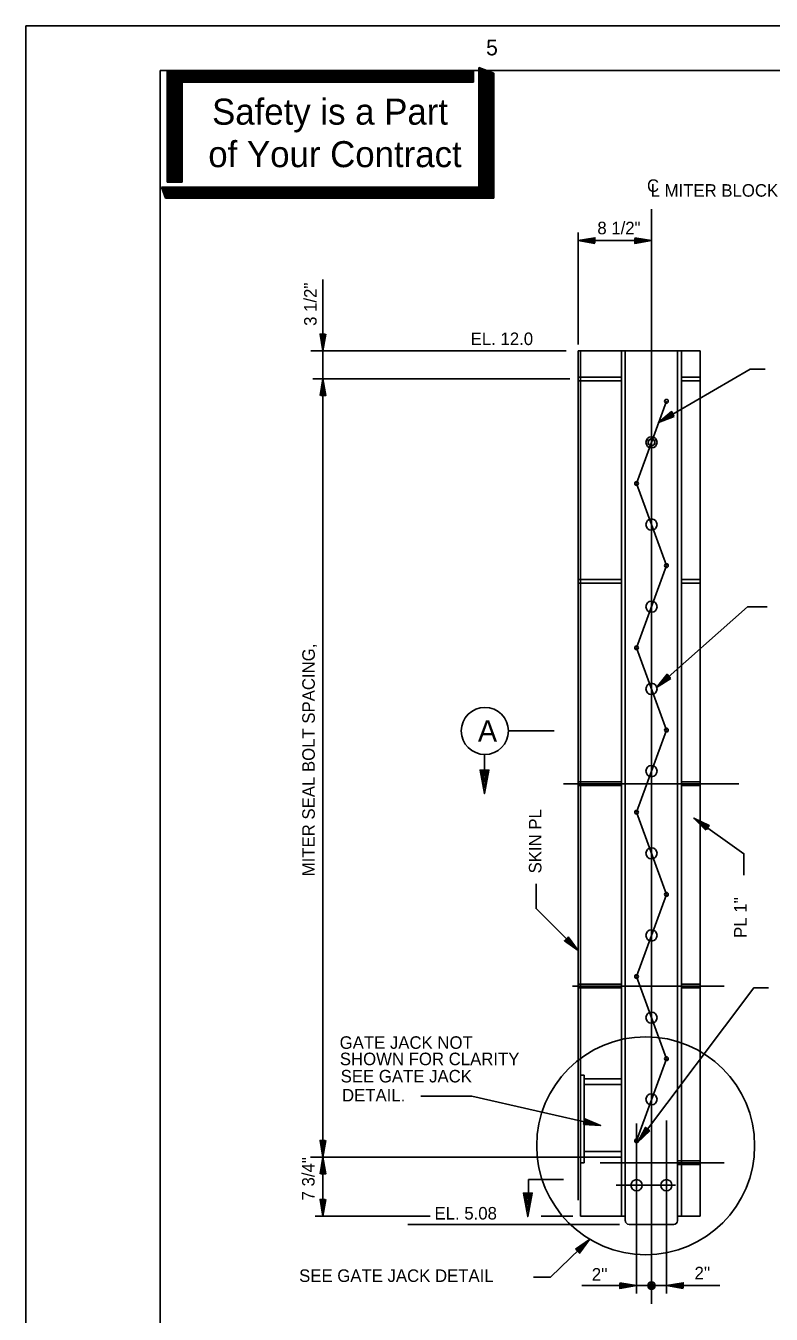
# Model space of a CAD drawing. Extents: x 0.04 to 6.71, y 0.04 to 4.71.
# Drawn here: x 0.042 to 1.428, y 2.312 to 4.708 of the extents above; entities that cross this region are included whole.
import ezdxf

# ---------------------------------------------------------------- set-up
doc = ezdxf.new("R2010")
doc.units = 0
for name, color, linetype in [('Level 1', 7, 'Continuous'), ('Level 13', 7, 'Continuous'), ('Level 25', 7, 'Continuous'), ('Level 3', 7, 'Continuous'), ('Level 50', 7, 'Continuous')]:
    doc.layers.add(name, color=color, linetype=linetype)

msp = doc.modelspace()

# ---------------------------------------------------------------- linework, layer by layer
at = {"layer": 'Level 1'}
for p, q in [((0.3045, 4.6245), (0.874, 4.6245)), ((0.3045, 4.6245), (0.3045, 4.4177)), ((0.3072, 4.6245), (0.3072, 4.4177)), ((0.3097, 4.6245), (0.3097, 4.4177)), ((0.3123, 4.6245), (0.3123, 4.4177)), ((0.3148, 4.6245), (0.3148, 4.4177)), ((0.3175, 4.6245), (0.3175, 4.4177)), ((0.3202, 4.6245), (0.3202, 4.4177)), ((0.3227, 4.6245), (0.3227, 4.4177)), ((0.3253, 4.6245), (0.3253, 4.4177)), ((0.328, 4.6245), (0.328, 4.4177)), ((0.3305, 4.6245), (0.3305, 4.4177)), ((0.874, 4.6245), (0.874, 4.6037)), ((0.8845, 4.6307), (0.8845, 4.4083)), ((0.8845, 4.6307), (0.9123, 4.6203)), ((0.8863, 4.63), (0.8863, 4.3875)), ((0.8888, 4.629), (0.8888, 4.3875)), ((0.8915, 4.628), (0.8915, 4.3875)), ((0.8942, 4.627), (0.8942, 4.3875)), ((0.8967, 4.6262), (0.8967, 4.3875)), ((0.8993, 4.6252), (0.8993, 4.3875)), ((0.3045, 4.6218), (0.874, 4.6218)), ((0.3045, 4.6193), (0.874, 4.6193)), ((0.3045, 4.6167), (0.874, 4.6167)), ((0.3045, 4.614), (0.874, 4.614)), ((0.3045, 4.6115), (0.874, 4.6115)), ((0.3045, 4.6088), (0.874, 4.6088)), ((0.3045, 4.6063), (0.874, 4.6063)), ((0.3323, 4.6037), (0.874, 4.6037)), ((0.3323, 4.6037), (0.3323, 4.4177)), ((0.9018, 4.6242), (0.9018, 4.3875)), ((0.9045, 4.6232), (0.9045, 4.3875)), ((0.9072, 4.6223), (0.9072, 4.3875)), ((0.9097, 4.6203), (0.9097, 4.3875)), ((0.9123, 4.6203), (0.9123, 4.3875)), ((0.3045, 4.4177), (0.3323, 4.4177)), ((0.294, 4.4083), (0.8845, 4.4083)), ((0.294, 4.4083), (0.3017, 4.3875)), ((0.295, 4.4057), (0.8863, 4.4057)), ((0.2958, 4.4032), (0.8863, 4.4032)), ((0.2968, 4.4005), (0.8863, 4.4005)), ((0.2978, 4.3978), (0.8863, 4.3978)), ((0.2988, 4.3953), (0.8863, 4.3953)), ((0.2998, 4.3927), (0.8863, 4.3927)), ((0.3007, 4.3902), (0.8863, 4.3902)), ((0.3017, 4.3875), (0.9123, 4.3875))]:
    msp.add_line(p, q, dxfattribs=at)
for points in [[(0.0417, 4.7083), (6.7083, 4.7083), (6.7083, 0.0417), (0.0417, 0.0417)], [(0.2917, 4.625), (6.625, 4.625), (6.625, 0.125), (0.2917, 0.125)]]:
    msp.add_lwpolyline(points, close=True, dxfattribs=at)
at = {"layer": 'Level 13'}
for p, q in [((1.2052, 3.9406), (1.1992, 3.9371)), ((1.1992, 3.9301), (1.1992, 3.9371)), ((1.2052, 3.9266), (1.1992, 3.9301)), ((1.2052, 3.9406), (1.2113, 3.9371)), ((1.2052, 3.9266), (1.2113, 3.9301)), ((1.2113, 3.9301), (1.2113, 3.9371))]:
    msp.add_line(p, q, dxfattribs=at)
msp.add_circle((1.2053, 3.9336), 0.00605, dxfattribs=at)
at = {"layer": 'Level 25'}
for p, q in [((1.2053, 4.3674), (1.2053, 2.3317)), ((1.0689, 4.1156), (1.0689, 4.3238)), ((1.0689, 4.3089), (1.2053, 4.3089)), ((0.5942, 4.1038), (0.5942, 4.2362)), ((0.572, 4.1038), (1.0469, 4.1038)), ((0.5942, 4.1038), (0.5942, 4.1038)), ((0.5942, 4.0517), (0.5942, 4.1038)), ((1.0689, 4.1038), (1.2955, 4.1038)), ((1.0689, 2.5245), (1.0689, 4.1038)), ((1.0733, 4.0551), (1.0733, 4.1038)), ((1.1497, 2.495), (1.1497, 4.1038)), ((1.1566, 2.4863), (1.1566, 4.1038)), ((1.2539, 2.4863), (1.2539, 4.1038)), ((1.2608, 2.495), (1.2608, 4.1038)), ((1.2955, 2.495), (1.2955, 4.1038)), ((0.5756, 4.0517), (1.0536, 4.0517)), ((0.5942, 4.0517), (0.5942, 4.0517)), ((0.5942, 2.6044), (0.5942, 4.0517)), ((0.5942, 4.0517), (0.5942, 4.0517)), ((1.0689, 4.0551), (1.1497, 4.0551)), ((1.0733, 4.0482), (1.0733, 4.0551)), ((1.2608, 4.0551), (1.2955, 4.0551)), ((1.0689, 4.0482), (1.1497, 4.0482)), ((1.0733, 3.6788), (1.0733, 4.0482)), ((1.2608, 4.0482), (1.2955, 4.0482)), ((1.233, 4.01), (1.1775, 3.8572)), ((1.1775, 3.8572), (1.233, 3.7044)), ((1.233, 3.7044), (1.1775, 3.5516)), ((1.0689, 3.6788), (1.1497, 3.6788)), ((1.0689, 3.6718), (1.1497, 3.6718)), ((1.0733, 3.6718), (1.0733, 3.6788)), ((1.0733, 3.3024), (1.0733, 3.6718)), ((1.2608, 3.6788), (1.2955, 3.6788)), ((1.2608, 3.6718), (1.2955, 3.6718)), ((1.1775, 3.5516), (1.233, 3.3987)), ((1.233, 3.3987), (1.1775, 3.2459)), ((1.3679, 3.2989), (1.0419, 3.2989)), ((1.1497, 3.3024), (1.0689, 3.3024)), ((1.1497, 3.2955), (1.0689, 3.2955)), ((1.0733, 3.2955), (1.0733, 3.3024)), ((1.0733, 2.926), (1.0733, 3.2955)), ((1.2955, 3.3024), (1.2608, 3.3024)), ((1.2955, 3.2955), (1.2608, 3.2955)), ((1.1775, 3.2459), (1.233, 3.0931)), ((1.233, 3.0931), (1.1775, 2.9403)), ((1.0689, 2.926), (1.1497, 2.926)), ((1.0733, 2.9191), (1.0733, 2.926)), ((1.1775, 2.9403), (1.233, 2.7875)), ((1.2608, 2.926), (1.2955, 2.926)), ((1.0581, 2.9226), (1.3404, 2.9226)), ((1.0689, 2.9191), (1.1497, 2.9191)), ((1.0733, 2.495), (1.0733, 2.9191)), ((1.2608, 2.9191), (1.2955, 2.9191)), ((1.233, 2.7875), (1.1775, 2.6347)), ((1.0733, 2.7572), (1.0802, 2.7572)), ((1.0802, 2.5939), (1.0802, 2.7572)), ((1.0802, 2.7502), (1.1497, 2.7502)), ((1.0802, 2.7398), (1.1497, 2.7398)), ((0.7766, 2.7176), (0.8711, 2.7176)), ((0.8711, 2.7176), (1.1107, 2.6636)), ((1.1775, 2.6671), (1.1775, 2.3511)), ((1.233, 2.6723), (1.233, 2.3511)), ((1.0802, 2.6148), (1.1497, 2.6148)), ((0.5711, 2.6044), (1.0802, 2.6044)), ((0.5942, 2.6044), (0.5942, 2.4946)), ((1.0733, 2.5939), (1.0802, 2.5939)), ((1.0802, 2.6044), (1.1497, 2.6044)), ((1.1098, 2.5939), (1.3404, 2.5939)), ((1.1566, 2.5939), (1.2539, 2.5939)), ((1.2539, 2.5974), (1.2955, 2.5974)), ((1.2539, 2.5905), (1.2955, 2.5905)), ((0.9765, 2.5626), (1.0414, 2.5626)), ((1.1399, 2.5523), (1.2502, 2.5523)), ((0.5797, 2.4946), (0.7939, 2.4946)), ((1.0001, 2.495), (1.059, 2.495)), ((1.0733, 2.495), (1.1566, 2.495)), ((1.2539, 2.495), (1.2955, 2.495)), ((0.7519, 2.4793), (1.1461, 2.4793)), ((1.1636, 2.4793), (1.2469, 2.4793)), ((1.0759, 2.3656), (1.1775, 2.3656)), ((1.1775, 2.3656), (1.1775, 2.3656)), ((1.1775, 2.3656), (1.2053, 2.3656)), ((1.2053, 2.3656), (1.2053, 2.3656)), ((1.2053, 2.3656), (1.233, 2.3656)), ((1.233, 2.3656), (1.233, 2.3656)), ((1.233, 2.3656), (1.3324, 2.3656))]:
    msp.add_line(p, q, dxfattribs=at)
for centre, radius in [((1.233, 4.01), 0.00347), ((1.2053, 3.9336), 0.0104), ((1.1775, 3.8572), 0.00347), ((1.2053, 3.7808), 0.0104), ((1.233, 3.7044), 0.00347), ((1.2053, 3.628), 0.0104), ((1.1775, 3.5516), 0.00347), ((1.2053, 3.4752), 0.0104), ((1.233, 3.3987), 0.00347), ((1.2053, 3.3223), 0.0104), ((1.1775, 3.2459), 0.00347), ((1.2053, 3.1695), 0.0104), ((1.233, 3.0931), 0.00347), ((1.2053, 3.0167), 0.0104), ((1.1775, 2.9403), 0.00347), ((1.2053, 2.8639), 0.0104), ((1.1945, 2.6257), 0.2026), ((1.233, 2.7875), 0.00347), ((1.2053, 2.712), 0.0104), ((1.1775, 2.6347), 0.00347), ((1.1775, 2.5523), 0.0104), ((1.233, 2.5523), 0.0104)]:
    msp.add_circle(centre, radius, dxfattribs=at)
for centre, start, end in [((1.1636, 2.4863), 180, 270), ((1.2469, 2.4863), 270, 0)]:
    msp.add_arc(centre, 0.00695, start, end, dxfattribs=at)
at = {"layer": 'Level 3'}
for p, q in [((1.2181, 3.9707), (1.2181, 3.9707)), ((1.2256, 3.975), (1.2256, 3.975)), ((1.2143, 3.4779), (1.2143, 3.4779)), ((1.2208, 3.4837), (1.2208, 3.4837)), ((1.0243, 3.397), (0.9383, 3.397)), ((0.8946, 3.3241), (0.8946, 3.3533)), ((1.2841, 3.2351), (1.2841, 3.2351)), ((1.2912, 3.2301), (1.2912, 3.2301)), ((0.9765, 2.5335), (0.9765, 2.5626)), ((1.0837, 2.4452), (1.0837, 2.4452)), ((1.0899, 2.4513), (1.0899, 2.4513))]:
    msp.add_line(p, q, dxfattribs=at)
for points in [[(1.4166, 4.07), (1.3888, 4.07), (1.2181, 3.9707)], [(1.2477, 3.9819), (1.2181, 3.9707), (1.2425, 3.9908), (1.2469, 3.9832), (1.2256, 3.975), (1.2422, 3.9887), (1.245, 3.9838), (1.2328, 3.9792), (1.2418, 3.9866), (1.243, 3.9846), (1.2403, 3.9836)], [(1.4204, 3.6276), (1.3838, 3.6276), (1.2143, 3.4779)], [(1.2411, 3.4947), (1.2143, 3.4779), (1.2343, 3.5024), (1.2401, 3.4958), (1.2208, 3.4837), (1.2344, 3.5003), (1.2381, 3.4961), (1.2271, 3.4892), (1.2345, 3.4982), (1.236, 3.4964), (1.2336, 3.4949)], [(0.9007, 3.3241), (0.9029, 3.3241), (0.8946, 3.2804), (0.8864, 3.3241), (0.9007, 3.3241), (0.8948, 3.2915), (0.8889, 3.322), (0.8983, 3.322), (0.8948, 3.3025), (0.8915, 3.32), (0.8959, 3.32), (0.8948, 3.3137), (0.894, 3.3178)], [(1.3772, 3.1286), (1.3772, 3.1686), (1.2841, 3.2351)], [(1.3065, 3.2128), (1.2841, 3.2351), (1.3125, 3.2212), (1.3074, 3.214), (1.2912, 3.2301), (1.3104, 3.2206), (1.3071, 3.216), (1.298, 3.2252), (1.3084, 3.22), (1.307, 3.2181), (1.305, 3.2202)], [(0.9907, 3.1128), (0.9907, 3.0668), (1.0689, 2.9885)], [(1.4229, 2.9191), (1.3955, 2.9191), (1.1794, 2.6318)], [(0.9814, 2.5376), (0.9836, 2.5376), (0.9753, 2.4939), (0.9671, 2.5376), (0.9814, 2.5376), (0.9754, 2.505), (0.9696, 2.5355), (0.979, 2.5355), (0.9754, 2.516), (0.9721, 2.5335), (0.9765, 2.5335), (0.9754, 2.5272), (0.9746, 2.5313)], [(0.9859, 2.3811), (1.0173, 2.3811), (1.0899, 2.4513)], [(1.0639, 2.4333), (1.0899, 2.4513), (1.0711, 2.4259), (1.0649, 2.4322), (1.0837, 2.4452), (1.0709, 2.428), (1.0669, 2.4321), (1.0777, 2.4394), (1.0707, 2.4301), (1.0691, 2.4318), (1.0714, 2.4334)]]:
    msp.add_lwpolyline(points, dxfattribs=at)
msp.add_circle((0.8954, 3.397), 0.0438, dxfattribs=at)
at = {"layer": 'Level 50'}
for p, q in [((1.0689, 4.3089), (1.0689, 4.3089)), ((1.0776, 4.3089), (1.0776, 4.3089)), ((1.1966, 4.3089), (1.1966, 4.3089)), ((1.2053, 4.3089), (1.2053, 4.3089)), ((0.5942, 4.1124), (0.5942, 4.1124)), ((0.5942, 4.1038), (0.5942, 4.1038)), ((0.5942, 4.0517), (0.5942, 4.0517)), ((0.5942, 4.043), (0.5942, 4.043)), ((1.0628, 2.9946), (1.0628, 2.9946)), ((1.0689, 2.9885), (1.0689, 2.9885)), ((1.1022, 2.6655), (1.1022, 2.6655)), ((1.1107, 2.6636), (1.1107, 2.6636)), ((1.1846, 2.6388), (1.1846, 2.6388)), ((0.5942, 2.613), (0.5942, 2.613)), ((1.1794, 2.6318), (1.1794, 2.6318)), ((0.5942, 2.6044), (0.5942, 2.6044)), ((0.5942, 2.6044), (0.5942, 2.6044)), ((0.5942, 2.5957), (0.5942, 2.5957)), ((0.5942, 2.5033), (0.5942, 2.5033)), ((0.5942, 2.4946), (0.5942, 2.4946)), ((1.1688, 2.3656), (1.1688, 2.3656)), ((1.1775, 2.3656), (1.1775, 2.3656)), ((1.233, 2.3656), (1.233, 2.3656)), ((1.2417, 2.3656), (1.2417, 2.3656))]:
    msp.add_line(p, q, dxfattribs=at)
for points in [[(1.1001, 4.3037), (1.0689, 4.3089), (1.1001, 4.3141), (1.1001, 4.3052), (1.0776, 4.3089), (1.0988, 4.3124), (1.0988, 4.3067), (1.0859, 4.3089), (1.0974, 4.3107), (1.0974, 4.3084), (1.0946, 4.3089)], [(1.1741, 4.3141), (1.2053, 4.3089), (1.1741, 4.3037), (1.1741, 4.3126), (1.1966, 4.3089), (1.1754, 4.3054), (1.1754, 4.3111), (1.1883, 4.3089), (1.1768, 4.3071), (1.1768, 4.3094), (1.1796, 4.3089)], [(0.5994, 4.1349), (0.5942, 4.1038), (0.589, 4.1349), (0.5979, 4.1349), (0.5942, 4.1124), (0.5907, 4.1336), (0.5964, 4.1336), (0.5942, 4.1208), (0.5924, 4.1323), (0.5947, 4.1323), (0.5942, 4.1294)], [(0.589, 4.0205), (0.5942, 4.0517), (0.5994, 4.0205), (0.5905, 4.0205), (0.5942, 4.043), (0.5977, 4.0218), (0.592, 4.0218), (0.5942, 4.0347), (0.596, 4.0232), (0.5937, 4.0232), (0.5942, 4.026)], [(1.0506, 3.0142), (1.0689, 2.9885), (1.0433, 3.0069), (1.0495, 3.0132), (1.0628, 2.9946), (1.0454, 3.0071), (1.0494, 3.0111), (1.0569, 3.0005), (1.0475, 3.0074), (1.0492, 3.009), (1.0508, 3.0067)], [(1.0814, 2.6755), (1.1107, 2.6636), (1.0791, 2.6654), (1.0811, 2.674), (1.1022, 2.6655), (1.0808, 2.6667), (1.082, 2.6723), (1.0941, 2.6673), (1.0825, 2.6681), (1.083, 2.6703), (1.0856, 2.6692)], [(1.2023, 2.6536), (1.1794, 2.6318), (1.194, 2.6598), (1.2011, 2.6545), (1.1846, 2.6388), (1.1945, 2.6578), (1.1991, 2.6544), (1.1896, 2.6454), (1.1951, 2.6557), (1.1969, 2.6543), (1.1948, 2.6523)], [(0.5994, 2.6355), (0.5942, 2.6044), (0.589, 2.6355), (0.5979, 2.6355), (0.5942, 2.613), (0.5907, 2.6342), (0.5964, 2.6342), (0.5942, 2.6214), (0.5924, 2.6329), (0.5947, 2.6329), (0.5942, 2.63)], [(0.589, 2.5732), (0.5942, 2.6044), (0.5994, 2.5732), (0.5905, 2.5732), (0.5942, 2.5957), (0.5977, 2.5745), (0.592, 2.5745), (0.5942, 2.5874), (0.596, 2.5759), (0.5937, 2.5759), (0.5942, 2.5787)], [(0.5994, 2.5258), (0.5942, 2.4946), (0.589, 2.5258), (0.5979, 2.5258), (0.5942, 2.5033), (0.5907, 2.5245), (0.5964, 2.5245), (0.5942, 2.5116), (0.5924, 2.5231), (0.5947, 2.5231), (0.5942, 2.5203)], [(1.1463, 2.3708), (1.1775, 2.3656), (1.1463, 2.3604), (1.1463, 2.3693), (1.1688, 2.3656), (1.1476, 2.3621), (1.1476, 2.3678), (1.1605, 2.3656), (1.149, 2.3638), (1.149, 2.3661), (1.1518, 2.3656)], [(1.2642, 2.3604), (1.233, 2.3656), (1.2642, 2.3708), (1.2642, 2.3619), (1.2417, 2.3656), (1.2629, 2.3691), (1.2629, 2.3634), (1.25, 2.3656), (1.2615, 2.3674), (1.2615, 2.3651), (1.2587, 2.3656)]]:
    msp.add_lwpolyline(points, dxfattribs=at)
for radius in [0.00703, 0.00439, 0.00176]:
    msp.add_circle((1.2053, 2.3656), radius, dxfattribs=at)

# ---------------------------------------------------------------- texts
at = {"layer": 'Level 1'}
for s, height, p in [('5', 0.0292, (0.8978, 4.6533)), ('Safety is a Part', 0.048396, (0.3881, 4.5244)), ('of Your Contract', 0.048396, (0.3811, 4.4454))]:
    msp.add_text(s, height=height, dxfattribs=at).set_placement(p)
at = {"layer": 'Level 25'}
for s, height, p in [('C', 0.0233, (1.1969, 4.3994)), ('L MITER BLOCK SEAL BOLTS', 0.023292, (1.2037, 4.3905)), ('8 1/2"', 0.02329, (1.1046, 4.3206)), ('EL. 12.0', 0.02329, (0.8691, 4.1146)), ('A', 0.04, (0.8825, 3.377)), ('GATE JACK NOT', 0.023292, (0.6254, 2.8059)), ('SHOWN FOR CLARITY', 0.023292, (0.6257, 2.7755)), ('SEE GATE JACK', 0.023292, (0.6273, 2.7434)), ('DETAIL.', 0.02329, (0.6298, 2.708)), ('EL. 5.08', 0.02329, (0.8018, 2.4885)), ('SEE GATE JACK DETAIL', 0.023292, (0.55, 2.3724)), ("2''", 0.02329, (1.0943, 2.3749)), ("2''", 0.02329, (1.2854, 2.3773))]:
    msp.add_text(s, height=height, dxfattribs=at).set_placement(p)
for s, height, p in [('3 1/2"', 0.02329, (0.5825, 4.1503)), ('MITER SEAL BOLT SPACING,', 0.023292, (0.5792, 3.1267)), ('SKIN PL', 0.02329, (1.0006, 3.1321)), ("PL 1''", 0.02329, (1.3822, 3.0122)), ('7 3/4"', 0.02329, (0.5787, 2.524))]:
    msp.add_text(s, height=height, rotation=90, dxfattribs=at).set_placement(p)

doc.saveas('drawing.dxf')
